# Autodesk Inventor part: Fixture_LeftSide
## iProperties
Shininess: 64.0
Length Units: 11269
Angle Units: 11279
Time Units: 11290
Mass Units: 11286
Length Display Precision: 3
Angle Display Precision: 2
Compacted: True
Part Number: Fixture_LeftSide
Document SubType Name: Modeling
Created: 2003-06
Designer: Administrator
Manufacturer: Standard
Standards Organization: Custom
Density: 1 g/cm^3
Density: 0.0
Volumn: 0.0
Area: 0.0
PropertySet Name: Model Information
Control State: 0
Master: False
Checked Out: False
Author: Administrator
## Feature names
1. Extrusion1
2. Extrusion2
3. Hole1
